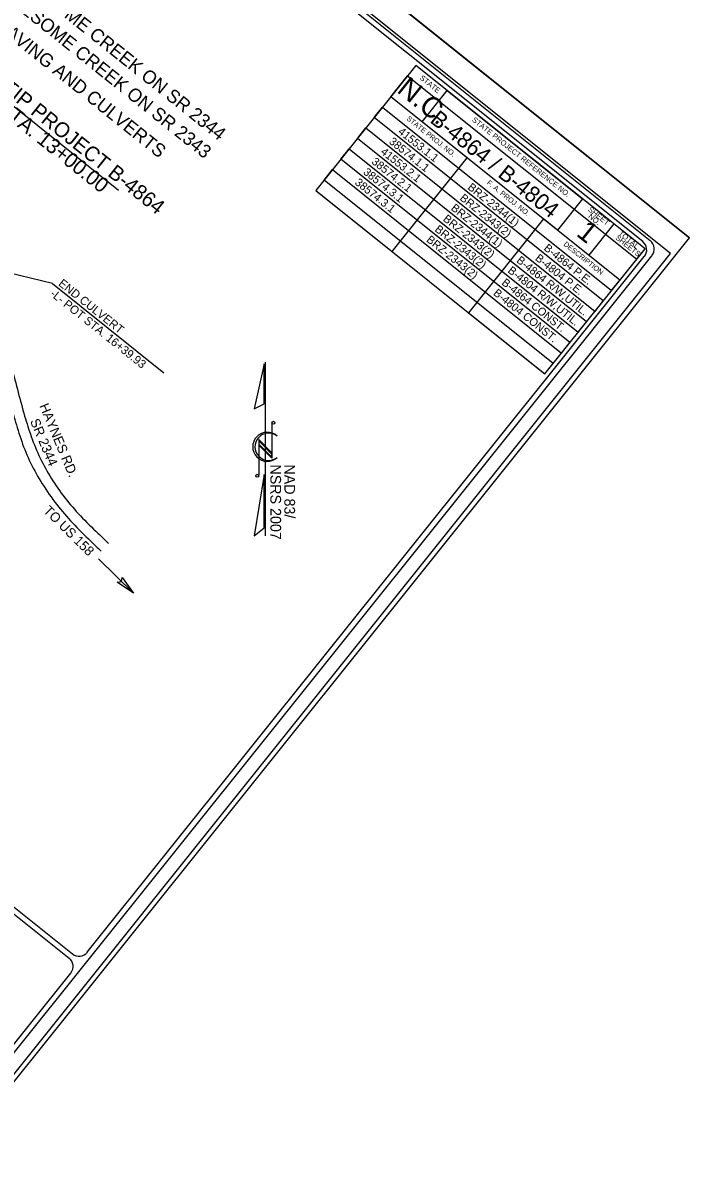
# Model space of a CAD drawing. Extents: x 1730256 to 1738218, y 910410 to 917906.
# Drawn here: x 1735520 to 1736769, y 913906 to 916027 of the extents above; entities that cross this region are included whole.
import ezdxf

# ---------------------------------------------------------------- set-up
doc = ezdxf.new("R2010")
doc.units = 0
for name, color, linetype in [('Old_Level_3', 7, 'Continuous'), ('Old_Level_9', 7, 'Continuous'), ('Prop DSN Text', 7, 'Continuous'), ('Prop Terminator CELL', 7, 'Continuous'), ('Sheet Cutting Line CELL', 7, 'Continuous'), ('Sheet Data Field CELL', 7, 'Continuous'), ('Sheet North Arrow CELL', 7, 'Continuous'), ('Sheet Plot Border Inside CELL', 7, 'Continuous'), ('Sheet Title CELL', 7, 'Continuous')]:
    doc.layers.add(name, color=color, linetype=linetype)

msp = doc.modelspace()

# ---------------------------------------------------------------- linework, layer by layer
at = {"layer": 'Old_Level_3'}
for points in [[(1735388.4, 915590.4), (1735416.8, 915551.2), (1735441.8, 915513.8), (1735465.3, 915471.6), (1735485, 915425.8), (1735499.5, 915381.4), (1735512.1, 915334.5), (1735524.2, 915290), (1735536.6, 915251.7), (1735553.3, 915211.2), (1735574, 915173.6), (1735599.6, 915136.9), (1735628.5, 915103.2), (1735661.8, 915070.2), (1735681.4, 915051.5)], [(1735374.5, 915580.4), (1735401.4, 915540.4), (1735425.3, 915502.3), (1735446.7, 915462.8), (1735465.8, 915420.2), (1735480.6, 915373.8), (1735493.3, 915328), (1735505.8, 915283.9), (1735518.6, 915242.7), (1735535.2, 915202.7), (1735557.3, 915162.9), (1735584.3, 915124.3), (1735613.8, 915089.7), (1735647.9, 915055.6), (1735667.7, 915037)]]:
    msp.add_spline(points, degree=3, dxfattribs=at)
at = {"layer": 'Old_Level_9'}
msp.add_line((1735662.7, 915022.6), (1735727.9, 914957.9), dxfattribs=at)
at = {"layer": 'Prop DSN Text'}
for p, q in [((1735349.1, 915994.4), (1735700, 915713.5)), ((1735576.1, 915538.3), (1735382.4, 915585.2)), ((1735576.1, 915538.3), (1735784.9, 915371.3))]:
    msp.add_line(p, q, dxfattribs=at)
at = {"layer": 'Prop Terminator CELL'}
msp.add_lwpolyline([(1735706.7, 914987.6), (1735727.9, 914957.9), (1735697.7, 914978.8), (1735705.5, 914980.1)], close=True, dxfattribs=at)
at = {"layer": 'Sheet Cutting Line CELL'}
msp.add_line((1734139.9, 917728.5), (1736769.5, 915624), dxfattribs=at)
at = {"layer": 'Sheet Data Field CELL'}
msp.add_lwpolyline([(1736769.5, 915624), (1734139.9, 917728.5), (1732765.3, 916010.8), (1735394.8, 913906.4)], close=True, dxfattribs=at)
at = {"layer": 'Sheet North Arrow CELL'}
for p, q in [((1735975.2, 915065.8), (1735975.2, 915390.8)), ((1735987.5, 915277.7), (1735987.5, 915211)), ((1735996.7, 915252.8), (1735997, 915252.6)), ((1735987.5, 915221.4), (1735962.6, 915246.2)), ((1735962.6, 915246.2), (1735962.6, 915178.4)), ((1735987.5, 915218.9), (1735962.6, 915243.8)), ((1735962.6, 915243.8), (1735962.6, 915237.7)), ((1735987.5, 915212.8), (1735962.6, 915237.7)), ((1735962.6, 915237.7), (1735987.5, 915212.8)), ((1735987.5, 915211), (1735962.6, 915235.8)), ((1735987.5, 915212.8), (1735987.5, 915218.9))]:
    msp.add_line(p, q, dxfattribs=at)
for points in [[(1735973, 915387.9), (1735954.4, 915303.5), (1735973, 915312.9)], [(1735972.6, 915180.3), (1735954.2, 915065.8), (1735972.6, 915080.3)]]:
    msp.add_lwpolyline(points, close=True, dxfattribs=at)
for centre in [(1735990.1, 915277.6), (1735960, 915178.3)]:
    msp.add_circle(centre, 2.65, dxfattribs=at)
for centre, radius, start, end in [((1735978.7, 915232.4), 27.3, 47.84, 312.3941), ((1735981.3, 915232.4), 25.6, 53.095, 308.6287)]:
    msp.add_arc(centre, radius, start, end, dxfattribs=at)
at = {"layer": 'Sheet Plot Border Inside CELL'}
msp.add_lwpolyline([(1732813.6, 916029.6), (1735415.9, 913947), (1736734.4, 915594.6), (1734132.1, 917677.2)], close=True, dxfattribs=at)
at = {"layer": 'Sheet Title CELL'}
for p, q in [((1733396.2, 916056.6), (1735613.6, 914282.1)), ((1735364.9, 914468.3), (1735607.3, 914274.3))]:
    msp.add_line(p, q, dxfattribs=at)
for points in [[(1736696.1, 915618.7), (1734385, 917468.3)], [(1736682, 915617.2), (1734464.7, 917391.7)], [(1736069.5, 915712.9), (1736498.9, 915369.2), (1736514.5, 915388.7), (1736085.2, 915732.4), (1736100.8, 915751.9), (1736530.2, 915408.2), (1736545.8, 915427.8), (1736116.4, 915771.4), (1736132, 915791), (1736561.4, 915447.3), (1736577, 915466.8), (1736147.6, 915810.5), (1736163.2, 915830), (1736592.7, 915486.3), (1736608.3, 915505.8), (1736178.9, 915849.5), (1736194.5, 915869), (1736623.9, 915525.3), (1736639.5, 915544.9), (1736210.1, 915888.5), (1736241.4, 915927.6), (1736670.8, 915583.9), (1736686.4, 915603.4), (1736257, 915947.1), (1736069.5, 915712.9), (1736212.6, 915598.3), (1736353.2, 915774), (1736268.7, 915841.7), (1736315.5, 915900.2), (1736569.3, 915697.1), (1736522.4, 915638.6), (1736496.3, 915659.5), (1736355.8, 915483.8), (1736498.9, 915369.2), (1736686.4, 915603.4), (1736627.8, 915650.3), (1736581, 915591.7)], [(1735412, 913982.3), (1736699.2, 915590.6)], [(1735641.6, 914285.2), (1736685.1, 915589.1)], [(1735410.5, 913996.3), (1735610.4, 914246.2)]]:
    msp.add_lwpolyline(points, dxfattribs=at)
for centre, start, end in [((1736669.6, 915601.6), 321.3297, 51.3297), ((1736683.6, 915603.2), 321.3297, 51.3297), ((1735594.9, 914258.7), 321.3297, 51.3297), ((1735626.1, 914297.8), 231.3297, 321.3297)]:
    msp.add_arc(centre, 20, start, end, dxfattribs=at)

# ---------------------------------------------------------------- texts
at = {"layer": 'Prop DSN Text'}
for s, height, rotation, p in [('BEGIN TIP PROJECT B-4864', 28, 321.3297, (1735380.8, 915979.6)), ('-L- POT STA. 13+00.00', 28, 321.3297, (1735359.6, 915953)), ('END CULVERT', 15.75, 321.3297, (1735586.1, 915536.1)), ('-L- POT STA. 16+39.93', 15.75, 321.3297, (1735570.6, 915516.8)), ('HAYNES RD.', 18, 292.7046, (1735551.3, 915309.3)), ('SR 2344', 18, 292.7046, (1735534, 915280.8)), ('TO US 158', 18, 315.1962, (1735558.1, 915111.2))]:
    msp.add_text(s, height=height, rotation=rotation, dxfattribs=at).set_placement(p)
at = {"layer": 'Sheet Data Field CELL'}
for s, height, p in [('BRIDGE NO. 13 OVER TROUBLESOME CREEK ON SR 2344', 25, (1735157.2, 916390.2)), ('BRIDGE NO. 12 OVER TROUBLESOME CREEK ON SR 2343', 25, (1735130, 916356.3)), ('GRADING, DRAINAGE, PAVING AND CULVERTS', 25, (1735181.5, 916248.4)), ('B-4864 / B-4804', 30, (1736281.7, 915842)), ('41553.1.1', 15, (1736222.5, 915820.8)), ('38574.1.1', 15, (1736205.5, 915802.4)), ('41553.2.1', 15, (1736189.9, 915783)), ('38574.2.1', 15, (1736172.9, 915764.5)), ('38574.3.1', 15, (1736157.3, 915745)), ('38574.3.1', 15, (1736141.6, 915725.5)), ('BRZ-2344(1)', 15, (1736352.8, 915716.6)), ('BRZ-2343(2)', 15, (1736338.1, 915696.3)), ('BRZ-2344(1)', 15, (1736321.6, 915677.6)), ('BRZ-2343(2)', 15, (1736306.8, 915657.3)), ('BRZ-2343(2)', 15, (1736291.2, 915637.8)), ('BRZ-2343(2)', 15, (1736275.6, 915618.3)), ('B-4864 P.E.', 15, (1736495.5, 915602.6)), ('B-4864 R/W,UTIL.', 15, (1736444.3, 915579.6)), ('B-4804 P.E.', 15, (1736479.3, 915583.6)), ('B-4804 R/W,UTIL.', 15, (1736428, 915560.6)), ('B-4864 CONST.', 15, (1736416.5, 915537.8)), ('B-4804 CONST.', 15, (1736400.9, 915518.3))]:
    msp.add_text(s, height=height, rotation=321.3297, dxfattribs=at).set_placement(p)
at = {"layer": 'Sheet North Arrow CELL'}
for s, p in [('NSRS 2007', (1735984.6, 915199.4)), ('NAD 83/', (1736010.8, 915199.4))]:
    msp.add_text(s, height=20, rotation=270, dxfattribs=at).set_placement(p)
at = {"layer": 'Sheet Title CELL'}
for s, height, p in [('STATE', 10, (1736263.3, 915922.2)), ('N.C.', 38.7, (1736219.8, 915898.3)), ('STATE PROJ. NO.', 9.6, (1736238.7, 915846)), ('STATE PROJECT REFERENCE NO.', 10, (1736361.4, 915843.6)), ('F. A. PROJ. NO.', 9.6, (1736389.1, 915725.7)), ('SHEET', 10, (1736578.7, 915675.5)), ('NO.', 10, (1736579, 915662.6)), ('1', 38.7, (1736555.7, 915629.5)), ('TOTAL', 10, (1736635.7, 915630.8)), ('DESCRIPTION', 9.6, (1736532.9, 915610.6)), ('SHEETS', 10, (1736630, 915622.6))]:
    msp.add_text(s, height=height, rotation=321.3297, dxfattribs=at).set_placement(p)

doc.saveas('drawing.dxf')
